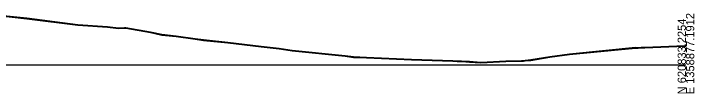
# Model space of a CAD drawing. Extents: x -26 to 803, y -27 to 3586.
# Drawn here: x 573.5 to 802.8, y 1490.3 to 1517.3 of the extents above; entities that cross this region are included whole.
import ezdxf

# ---------------------------------------------------------------- set-up
doc = ezdxf.new("R2010")
doc.units = 0
for name, color, linetype in [('DESIGN - SHEET - Light Grid', 7, 'Continuous'), ('SURVEY - GROUND - Bottom of Topsoil Layer', 7, 'Continuous'), ('SURVEY - GROUND - Top of Ground', 7, 'Continuous')]:
    doc.layers.add(name, color=color, linetype=linetype)

msp = doc.modelspace()

# ---------------------------------------------------------------- linework, layer by layer
at = {"layer": 'DESIGN - SHEET - Light Grid'}
msp.add_line((400, 1500), (800, 1500), dxfattribs=at)
at = {"layer": 'SURVEY - GROUND - Bottom of Topsoil Layer'}
for p, q in [((565.53, 1516.88), (578.05, 1515.55)), ((578.05, 1515.55), (595.2, 1513.4)), ((595.2, 1513.4), (605.19, 1512.67)), ((605.19, 1512.67), (608.86, 1512.24)), ((608.86, 1512.24), (610.95, 1512.32)), ((610.95, 1512.32), (611.29, 1512.32)), ((611.29, 1512.32), (619.69, 1510.88)), ((619.69, 1510.88), (623.43, 1510.05)), ((623.43, 1510.05), (628.3, 1509.52)), ((628.3, 1509.52), (634.7, 1508.66)), ((634.7, 1508.66), (637.55, 1508.25)), ((637.55, 1508.25), (645.66, 1507.41)), ((645.66, 1507.41), (656.92, 1506.05)), ((656.92, 1506.05), (663, 1505.35)), ((663, 1505.35), (667.41, 1504.7)), ((667.41, 1504.7), (685.26, 1502.87)), ((760.73, 1503.49), (782.97, 1505.64)), ((782.97, 1505.64), (783.91, 1505.61)), ((783.91, 1505.61), (784.86, 1505.72)), ((784.86, 1505.72), (786.2, 1505.74)), ((786.2, 1505.74), (799.57, 1506.23)), ((799.57, 1506.23), (800, 1506.25)), ((685.26, 1502.87), (688.03, 1502.49)), ((688.03, 1502.49), (689.22, 1502.43)), ((689.22, 1502.43), (690.21, 1502.4)), ((690.21, 1502.4), (692.44, 1502.31)), ((692.44, 1502.31), (707.52, 1501.68)), ((747.77, 1501.47), (754.17, 1502.51)), ((754.17, 1502.51), (760.73, 1503.49)), ((707.52, 1501.68), (721.43, 1501.17)), ((721.43, 1501.17), (722.93, 1501.12)), ((722.93, 1501.12), (724.39, 1501.07)), ((724.39, 1501.07), (725.88, 1500.98)), ((725.88, 1500.98), (727.11, 1500.92)), ((727.11, 1500.92), (730.92, 1500.66)), ((730.92, 1500.66), (739.28, 1501.09)), ((739.28, 1501.09), (744.61, 1501.19)), ((744.61, 1501.19), (745.33, 1501.22)), ((745.33, 1501.22), (745.79, 1501.33)), ((745.79, 1501.33), (747.77, 1501.47))]:
    msp.add_line(p, q, dxfattribs=at)
at = {"layer": 'SURVEY - GROUND - Top of Ground'}
msp.add_lwpolyline([(565.53, 1517.13), (578.05, 1515.8), (595.2, 1513.65), (605.19, 1512.92), (608.86, 1512.49), (610.95, 1512.57), (611.29, 1512.57), (619.69, 1511.13), (623.43, 1510.3), (628.3, 1509.77), (634.7, 1508.91), (637.55, 1508.5), (645.66, 1507.66), (656.92, 1506.3), (663, 1505.6), (667.41, 1504.95), (685.26, 1503.12), (688.03, 1502.74), (689.22, 1502.68), (690.21, 1502.65), (692.44, 1502.56), (707.52, 1501.93), (721.43, 1501.42), (722.93, 1501.37), (724.39, 1501.32), (725.88, 1501.23), (727.11, 1501.17), (730.92, 1500.91), (739.28, 1501.34), (744.61, 1501.44), (745.33, 1501.47), (745.79, 1501.58), (747.77, 1501.72), (754.17, 1502.76), (760.73, 1503.74), (782.97, 1505.89), (783.91, 1505.86), (784.86, 1505.97), (786.2, 1505.99), (799.57, 1506.48), (800, 1506.5)], dxfattribs=at)

# ---------------------------------------------------------------- texts
at = {"layer": 'DESIGN - SHEET - Light Grid'}
for s, p in [('E 1358877.1912', (802.8, 1490)), ('N 620833.2254', (800, 1490))]:
    msp.add_text(s, height=2.8, rotation=90, dxfattribs=at).set_placement(p)

doc.saveas('drawing.dxf')
